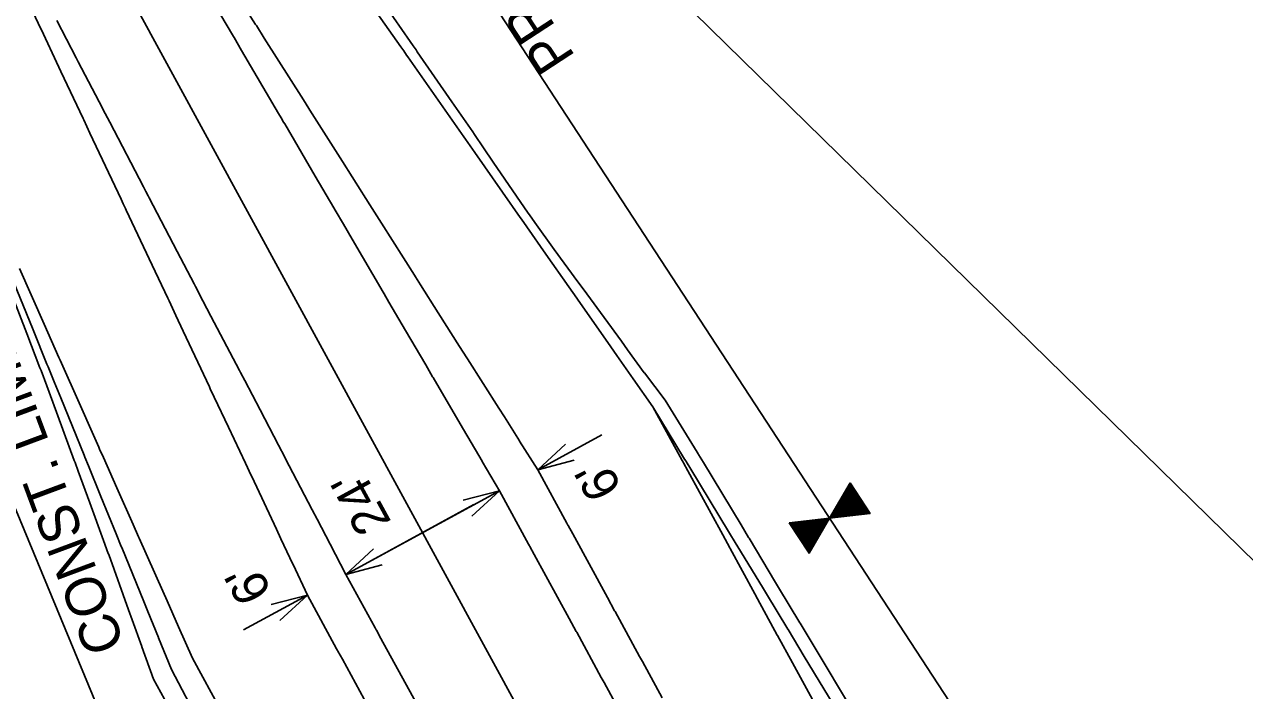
# Model space of a CAD drawing. Extents: x 1627557 to 1636561, y 783843 to 794002.
# Drawn here: x 1627879.8 to 1628047.3, y 785122 to 785213.4 of the extents above; entities that cross this region are included whole.
import ezdxf

# ---------------------------------------------------------------- set-up
doc = ezdxf.new("R2010")
doc.units = 0
for name, color, linetype in [('Dimensions', 7, 'Continuous'), ('GATE', 7, 'Continuous'), ('R_Clearzone', 7, 'Continuous'), ('R_Ditch', 7, 'Continuous'), ('R_Horz Alg', 7, 'Continuous'), ('R_Horz Alg Annot', 7, 'Continuous'), ('R_Proposed Const Limits', 7, 'Continuous'), ('R_Proposed Const Limits Annot', 7, 'Continuous'), ('R_Proposed Road', 7, 'Continuous'), ('R_Proposed Shoulder', 7, 'Continuous'), ('R_ROW', 7, 'Continuous'), ('R_ROW Annot Labels Ends', 7, 'Continuous'), ('R_Temp Const Easement', 7, 'Continuous')]:
    doc.layers.add(name, color=color, linetype=linetype)

msp = doc.modelspace()

# ---------------------------------------------------------------- linework, layer by layer
at = {"layer": 'Dimensions'}
for p, q in [((1627950.27, 785152.3), (1627959.05, 785157.08)), ((1627950.27, 785152.3), (1627954.06, 785155.79)), ((1627950.27, 785152.3), (1627955.26, 785153.59)), ((1627923.93, 785137.93), (1627945, 785149.42)), ((1627945, 785149.42), (1627940.02, 785148.13)), ((1627945, 785149.42), (1627941.22, 785145.93)), ((1627923.93, 785137.93), (1627927.72, 785141.42)), ((1627923.93, 785137.93), (1627928.92, 785139.23)), ((1627918.64, 785135.1), (1627909.87, 785130.31)), ((1627918.64, 785135.1), (1627913.66, 785133.8)), ((1627918.64, 785135.1), (1627914.86, 785131.61))]:
    msp.add_line(p, q, dxfattribs=at)
at = {"layer": 'GATE'}
for p, q in [((1627992.92, 785150.09), (1627995.43, 785146.26)), ((1627992.97, 785150.19), (1627995.54, 785146.27)), ((1627993.03, 785150.29), (1627995.65, 785146.28)), ((1627993.09, 785150.38), (1627995.76, 785146.29)), ((1627993.14, 785150.48), (1627995.87, 785146.31)), ((1627991.96, 785148.45), (1627993.54, 785146.04)), ((1627992.02, 785148.55), (1627993.65, 785146.05)), ((1627992.07, 785148.65), (1627993.76, 785146.06)), ((1627992.13, 785148.74), (1627993.87, 785146.07)), ((1627992.19, 785148.84), (1627993.98, 785146.09)), ((1627992.24, 785148.93), (1627994.09, 785146.1)), ((1627992.3, 785149.03), (1627994.21, 785146.11)), ((1627992.35, 785149.13), (1627994.32, 785146.13)), ((1627992.41, 785149.22), (1627994.43, 785146.14)), ((1627992.47, 785149.32), (1627994.54, 785146.15)), ((1627992.52, 785149.42), (1627994.65, 785146.16)), ((1627992.58, 785149.51), (1627994.76, 785146.18)), ((1627992.64, 785149.61), (1627994.87, 785146.19)), ((1627992.69, 785149.71), (1627994.98, 785146.2)), ((1627992.75, 785149.8), (1627995.09, 785146.22)), ((1627992.8, 785149.9), (1627995.2, 785146.23)), ((1627992.86, 785150), (1627995.32, 785146.24)), ((1627990.95, 785146.71), (1627991.54, 785145.8)), ((1627991, 785146.81), (1627991.65, 785145.82)), ((1627991.06, 785146.91), (1627991.76, 785145.83)), ((1627991.11, 785147), (1627991.87, 785145.84)), ((1627991.17, 785147.1), (1627991.98, 785145.86)), ((1627991.23, 785147.2), (1627992.1, 785145.87)), ((1627991.28, 785147.29), (1627992.21, 785145.88)), ((1627991.34, 785147.39), (1627992.32, 785145.89)), ((1627991.4, 785147.49), (1627992.43, 785145.91)), ((1627991.45, 785147.58), (1627992.54, 785145.92)), ((1627991.51, 785147.68), (1627992.65, 785145.93)), ((1627991.57, 785147.78), (1627992.76, 785145.95)), ((1627991.62, 785147.87), (1627992.87, 785145.96)), ((1627991.68, 785147.97), (1627992.98, 785145.97)), ((1627991.73, 785148.07), (1627993.09, 785145.98)), ((1627991.79, 785148.16), (1627993.21, 785146)), ((1627991.85, 785148.26), (1627993.32, 785146.01)), ((1627991.9, 785148.36), (1627993.43, 785146.02)), ((1627984.86, 785145.03), (1627987.56, 785140.91)), ((1627984.97, 785145.04), (1627987.61, 785141)), ((1627985.08, 785145.06), (1627987.67, 785141.1)), ((1627985.19, 785145.07), (1627987.73, 785141.19)), ((1627985.3, 785145.08), (1627987.78, 785141.29)), ((1627985.42, 785145.09), (1627987.84, 785141.39)), ((1627985.53, 785145.11), (1627987.9, 785141.48)), ((1627985.64, 785145.12), (1627987.95, 785141.58)), ((1627985.75, 785145.13), (1627988.01, 785141.68)), ((1627985.86, 785145.15), (1627988.06, 785141.77)), ((1627985.97, 785145.16), (1627988.12, 785141.87)), ((1627986.08, 785145.17), (1627988.18, 785141.97)), ((1627986.19, 785145.18), (1627988.23, 785142.06)), ((1627986.3, 785145.2), (1627988.29, 785142.16)), ((1627986.42, 785145.21), (1627988.35, 785142.26)), ((1627986.53, 785145.22), (1627988.4, 785142.35)), ((1627986.64, 785145.24), (1627988.46, 785142.45)), ((1627986.75, 785145.25), (1627988.51, 785142.55)), ((1627986.86, 785145.26), (1627988.57, 785142.64)), ((1627986.97, 785145.27), (1627988.63, 785142.74)), ((1627987.08, 785145.29), (1627988.68, 785142.84)), ((1627987.19, 785145.3), (1627988.74, 785142.93)), ((1627987.3, 785145.31), (1627988.8, 785143.03)), ((1627987.41, 785145.33), (1627988.85, 785143.13)), ((1627987.53, 785145.34), (1627988.91, 785143.22)), ((1627987.64, 785145.35), (1627988.97, 785143.32)), ((1627987.75, 785145.36), (1627989.02, 785143.42)), ((1627987.86, 785145.38), (1627989.08, 785143.51)), ((1627987.97, 785145.39), (1627989.13, 785143.61)), ((1627988.08, 785145.4), (1627989.19, 785143.71)), ((1627988.19, 785145.42), (1627989.25, 785143.8)), ((1627988.3, 785145.43), (1627989.3, 785143.9)), ((1627988.41, 785145.44), (1627989.36, 785144)), ((1627988.53, 785145.46), (1627989.42, 785144.09)), ((1627988.64, 785145.47), (1627989.47, 785144.19)), ((1627988.75, 785145.48), (1627989.53, 785144.29)), ((1627988.86, 785145.49), (1627989.59, 785144.38)), ((1627988.97, 785145.51), (1627989.64, 785144.48)), ((1627989.08, 785145.52), (1627989.7, 785144.57)), ((1627989.19, 785145.53), (1627989.75, 785144.67)), ((1627989.3, 785145.55), (1627989.81, 785144.77)), ((1627989.41, 785145.56), (1627989.87, 785144.86)), ((1627989.52, 785145.57), (1627989.92, 785144.96)), ((1627989.64, 785145.58), (1627989.98, 785145.06)), ((1627989.75, 785145.6), (1627990.04, 785145.15)), ((1627989.86, 785145.61), (1627990.09, 785145.25)), ((1627989.97, 785145.62), (1627990.15, 785145.35)), ((1627990.08, 785145.64), (1627990.21, 785145.44)), ((1627990.19, 785145.65), (1627990.26, 785145.54)), ((1627990.3, 785145.66), (1627990.32, 785145.64)), ((1627990.38, 785145.75), (1627990.43, 785145.68)), ((1627990.44, 785145.84), (1627990.54, 785145.69)), ((1627990.49, 785145.94), (1627990.65, 785145.7)), ((1627990.55, 785146.04), (1627990.76, 785145.71)), ((1627990.61, 785146.13), (1627990.87, 785145.73)), ((1627990.66, 785146.23), (1627990.98, 785145.74)), ((1627990.72, 785146.33), (1627991.1, 785145.75)), ((1627990.78, 785146.42), (1627991.21, 785145.77)), ((1627990.83, 785146.52), (1627991.32, 785145.78)), ((1627990.89, 785146.62), (1627991.43, 785145.79))]:
    msp.add_line(p, q, dxfattribs=at)
for points in [[(1627993.15, 785150.49), (1627990.33, 785145.66), (1627995.89, 785146.31)], [(1627984.78, 785145.02), (1627990.33, 785145.66), (1627987.52, 785140.84)]]:
    msp.add_lwpolyline(points, close=True, dxfattribs=at)
at = {"layer": 'R_Clearzone'}
for points in [[(1627989.61, 785117.75), (1627985.22, 785125.79), (1627983.17, 785129.56), (1627983.14, 785129.61), (1627980.44, 785134.57), (1627980.05, 785135.28), (1627976.68, 785141.47), (1627976.62, 785141.57), (1627975.65, 785143.35), (1627970.86, 785152.13), (1627970.25, 785153.25), (1627970.21, 785153.32), (1627970.07, 785153.58), (1627966.07, 785160.91), (1627963.38, 785164.76), (1627963.36, 785164.79), (1627961.14, 785167.96), (1627960.3, 785169.16), (1627955.71, 785175.73), (1627955.61, 785175.86), (1627954.53, 785177.4), (1627951.38, 785181.9), (1627948.76, 785185.64), (1627948.03, 785186.7), (1627947.86, 785186.93), (1627942.99, 785193.89), (1627941.62, 785195.84), (1627940.35, 785197.67), (1627940.12, 785198), (1627937.22, 785202.13), (1627932.43, 785208.98), (1627932.26, 785209.21), (1627931.87, 785209.78), (1627931.45, 785210.37), (1627925.68, 785218.62)], [(1627906.86, 785119.11), (1627902.86, 785126.45), (1627900.96, 785130.72), (1627900.95, 785130.75), (1627899.38, 785134.29), (1627898.79, 785135.62), (1627895.54, 785142.92), (1627895.48, 785143.07), (1627894.72, 785144.79), (1627892.49, 785149.8), (1627890.65, 785153.96), (1627890.13, 785155.13), (1627890.01, 785155.38), (1627886.57, 785163.13), (1627885.61, 785165.3), (1627884.71, 785167.33), (1627884.54, 785167.7), (1627882.5, 785172.3), (1627879.12, 785179.91)]]:
    msp.add_lwpolyline(points, dxfattribs=at)
at = {"layer": 'R_Ditch'}
for points in [[(1627991.6, 785118.84), (1627986.85, 785126.68), (1627984.62, 785130.35), (1627984.59, 785130.4), (1627981.66, 785135.24), (1627981.24, 785135.93), (1627977.58, 785141.96), (1627977.52, 785142.06), (1627976.47, 785143.8), (1627971.28, 785152.36), (1627970.62, 785153.44), (1627970.57, 785153.52), (1627970.42, 785153.77), (1627966.08, 785160.92), (1627963.38, 785164.76), (1627963.36, 785164.79), (1627961.14, 785167.96), (1627960.3, 785169.16), (1627955.71, 785175.73), (1627955.61, 785175.86), (1627954.53, 785177.4), (1627951.38, 785181.9), (1627948.76, 785185.64), (1627948.03, 785186.7), (1627947.86, 785186.93), (1627942.99, 785193.89), (1627941.62, 785195.84), (1627940.35, 785197.67), (1627940.12, 785198), (1627937.22, 785202.13), (1627932.43, 785208.98), (1627932.26, 785209.21), (1627931.87, 785209.78), (1627931.45, 785210.37), (1627925.68, 785218.62)], [(1627903.87, 785117.48), (1627899.98, 785124.87), (1627898.21, 785129.22), (1627898.2, 785129.25), (1627896.73, 785132.85), (1627896.18, 785134.19), (1627893.16, 785141.62), (1627893.1, 785141.77), (1627892.39, 785143.51), (1627890.31, 785148.61), (1627888.59, 785152.83), (1627888.11, 785154.03), (1627888, 785154.29), (1627884.79, 785162.15), (1627883.89, 785164.37), (1627883.05, 785166.43), (1627882.9, 785166.8), (1627881, 785171.48), (1627877.85, 785179.22)]]:
    msp.add_lwpolyline(points, dxfattribs=at)
at = {"layer": 'R_Horz Alg'}
msp.add_line((1628236.53, 784589.68), (1627810.31, 785371.39), dxfattribs=at)
at = {"layer": 'R_Horz Alg Annot'}
msp.add_lwpolyline([(1627927.44, 785139.85), (1627941.49, 785147.51)], dxfattribs=at)
at = {"layer": 'R_Proposed Const Limits'}
for points in [[(1627993.18, 785119.7), (1627988.48, 785127.57), (1627986.28, 785131.25), (1627986.24, 785131.3), (1627983.32, 785136.14), (1627982.9, 785136.83), (1627979.27, 785142.88), (1627979.21, 785142.98), (1627978.17, 785144.73), (1627973.01, 785153.3), (1627972.35, 785154.39), (1627972.3, 785154.46), (1627972.15, 785154.71), (1627967.76, 785161.83), (1627964.91, 785165.59), (1627964.89, 785165.62), (1627962.6, 785168.76), (1627961.74, 785169.94), (1627956.99, 785176.43), (1627956.9, 785176.56), (1627955.77, 785178.07), (1627952.53, 785182.53), (1627949.88, 785186.25), (1627949.14, 785187.3), (1627948.97, 785187.53), (1627944.13, 785194.51), (1627942.8, 785196.49), (1627941.57, 785198.33), (1627941.35, 785198.67), (1627938.49, 785202.82), (1627933.73, 785209.68), (1627933.56, 785209.92), (1627933.17, 785210.49), (1627932.76, 785211.08), (1627927.03, 785219.35)], [(1627901.57, 785116.23), (1627897.53, 785123.54), (1627895.94, 785127.98), (1627895.93, 785128.02), (1627894.6, 785131.68), (1627894.1, 785133.06), (1627891.37, 785140.65), (1627891.31, 785140.8), (1627890.65, 785142.57), (1627888.77, 785147.76), (1627887.2, 785152.08), (1627886.75, 785153.29), (1627886.65, 785153.55), (1627883.7, 785161.56), (1627882.88, 785163.82), (1627882.08, 785165.9), (1627881.94, 785166.28), (1627880.12, 785171), (1627877.1, 785178.81)]]:
    msp.add_lwpolyline(points, dxfattribs=at)
at = {"layer": 'R_Proposed Road'}
for points in [[(1627962.07, 785118.12), (1627959.36, 785123.08), (1627958.98, 785123.79), (1627955.61, 785129.98), (1627955.55, 785130.08), (1627954.58, 785131.86), (1627949.79, 785140.64), (1627949.18, 785141.76), (1627949.14, 785141.83), (1627949, 785142.09), (1627945, 785149.42), (1627942.65, 785153.45), (1627942.63, 785153.48), (1627940.68, 785156.81), (1627939.95, 785158.06), (1627935.92, 785164.94), (1627935.84, 785165.07), (1627934.89, 785166.69), (1627932.13, 785171.41), (1627929.84, 785175.32), (1627929.19, 785176.43), (1627929.05, 785176.67), (1627924.78, 785183.96), (1627923.58, 785186.01), (1627922.46, 785187.92), (1627922.26, 785188.26), (1627919.72, 785192.59), (1627915.53, 785199.76), (1627915.38, 785200.01), (1627915.03, 785200.6), (1627914.67, 785201.22), (1627909.61, 785209.86), (1627908.59, 785211.61), (1627908.5, 785211.76), (1627904.89, 785217.92)], [(1627933.51, 785120.38), (1627928.72, 785129.15), (1627928.11, 785130.27), (1627928.07, 785130.34), (1627927.93, 785130.6), (1627923.93, 785137.93), (1627921.77, 785142.07), (1627921.76, 785142.1), (1627919.97, 785145.52), (1627919.3, 785146.8), (1627915.61, 785153.87), (1627915.54, 785154.01), (1627914.67, 785155.67), (1627912.14, 785160.51), (1627910.04, 785164.53), (1627909.45, 785165.66), (1627909.32, 785165.91), (1627905.41, 785173.4), (1627904.31, 785175.5), (1627903.29, 785177.46), (1627903.1, 785177.82), (1627900.78, 785182.26), (1627896.94, 785189.63), (1627896.8, 785189.88), (1627896.48, 785190.49), (1627896.15, 785191.13), (1627891.52, 785199.99), (1627890.58, 785201.79), (1627890.5, 785201.94), (1627887.2, 785208.27), (1627886.89, 785208.86), (1627884.23, 785213.95)]]:
    msp.add_lwpolyline(points, dxfattribs=at)
at = {"layer": 'R_Proposed Shoulder'}
for points in [[(1627967.34, 785120.99), (1627964.63, 785125.96), (1627964.25, 785126.66), (1627960.87, 785132.85), (1627960.82, 785132.95), (1627959.85, 785134.74), (1627955.06, 785143.52), (1627954.45, 785144.63), (1627954.41, 785144.71), (1627954.27, 785144.96), (1627950.27, 785152.3), (1627947.77, 785156.24), (1627947.75, 785156.27), (1627945.68, 785159.54), (1627944.91, 785160.76), (1627940.63, 785167.51), (1627940.55, 785167.64), (1627939.54, 785169.23), (1627936.61, 785173.85), (1627934.18, 785177.69), (1627933.49, 785178.77), (1627933.34, 785179.01), (1627928.82, 785186.16), (1627927.54, 785188.17), (1627926.36, 785190.04), (1627926.14, 785190.38), (1627923.45, 785194.62), (1627919, 785201.65), (1627918.84, 785201.9), (1627918.47, 785202.48), (1627918.09, 785203.09), (1627912.72, 785211.55), (1627911.64, 785213.27), (1627911.54, 785213.41), (1627907.71, 785219.46)], [(1627928.24, 785117.5), (1627923.45, 785126.28), (1627922.84, 785127.4), (1627922.8, 785127.47), (1627922.66, 785127.73), (1627918.66, 785135.06), (1627916.68, 785139.29), (1627916.66, 785139.32), (1627915.01, 785142.82), (1627914.4, 785144.13), (1627911, 785151.35), (1627910.93, 785151.49), (1627910.13, 785153.19), (1627907.8, 785158.14), (1627905.87, 785162.25), (1627905.32, 785163.41), (1627905.2, 785163.67), (1627901.6, 785171.32), (1627900.59, 785173.47), (1627899.65, 785175.48), (1627899.47, 785175.84), (1627897.34, 785180.38), (1627893.79, 785187.91), (1627893.67, 785188.17), (1627893.38, 785188.8), (1627893.07, 785189.45), (1627888.8, 785198.51), (1627887.94, 785200.35), (1627887.87, 785200.5), (1627884.82, 785206.98), (1627884.54, 785207.58), (1627882.09, 785212.78), (1627882.06, 785212.84), (1627880.27, 785216.64)]]:
    msp.add_lwpolyline(points, dxfattribs=at)
at = {"layer": 'R_ROW'}
for p, q in [((1628058.95, 785040.71), (1627921.72, 785250.62)), ((1627959.18, 784952.13), (1627851.48, 785212.33))]:
    msp.add_line(p, q, dxfattribs=at)
at = {"layer": 'R_Temp Const Easement'}
msp.add_line((1628064.95, 785123.71), (1627930.5, 785255.41), dxfattribs=at)

# ---------------------------------------------------------------- texts
at = {"layer": 'Dimensions'}
for s, p in [("6'", (1627961.93, 785149.79)), ("24'", (1627930.23, 785145.11)), ("6'", (1627913.88, 785135.54))]:
    msp.add_text(s, height=5, rotation=118.601, dxfattribs=at).set_placement(p)
at = {"layer": 'R_Proposed Const Limits Annot'}
msp.add_text('CONST. LIMITS', height=5.5, rotation=110.4259, dxfattribs=at).set_placement((1627893.65, 785128.21))
at = {"layer": 'R_ROW Annot Labels Ends'}
msp.add_text('PROP. ROW', height=5.5, rotation=123.1751, dxfattribs=at).set_placement((1627955.51, 785208.99))

doc.saveas('drawing.dxf')
